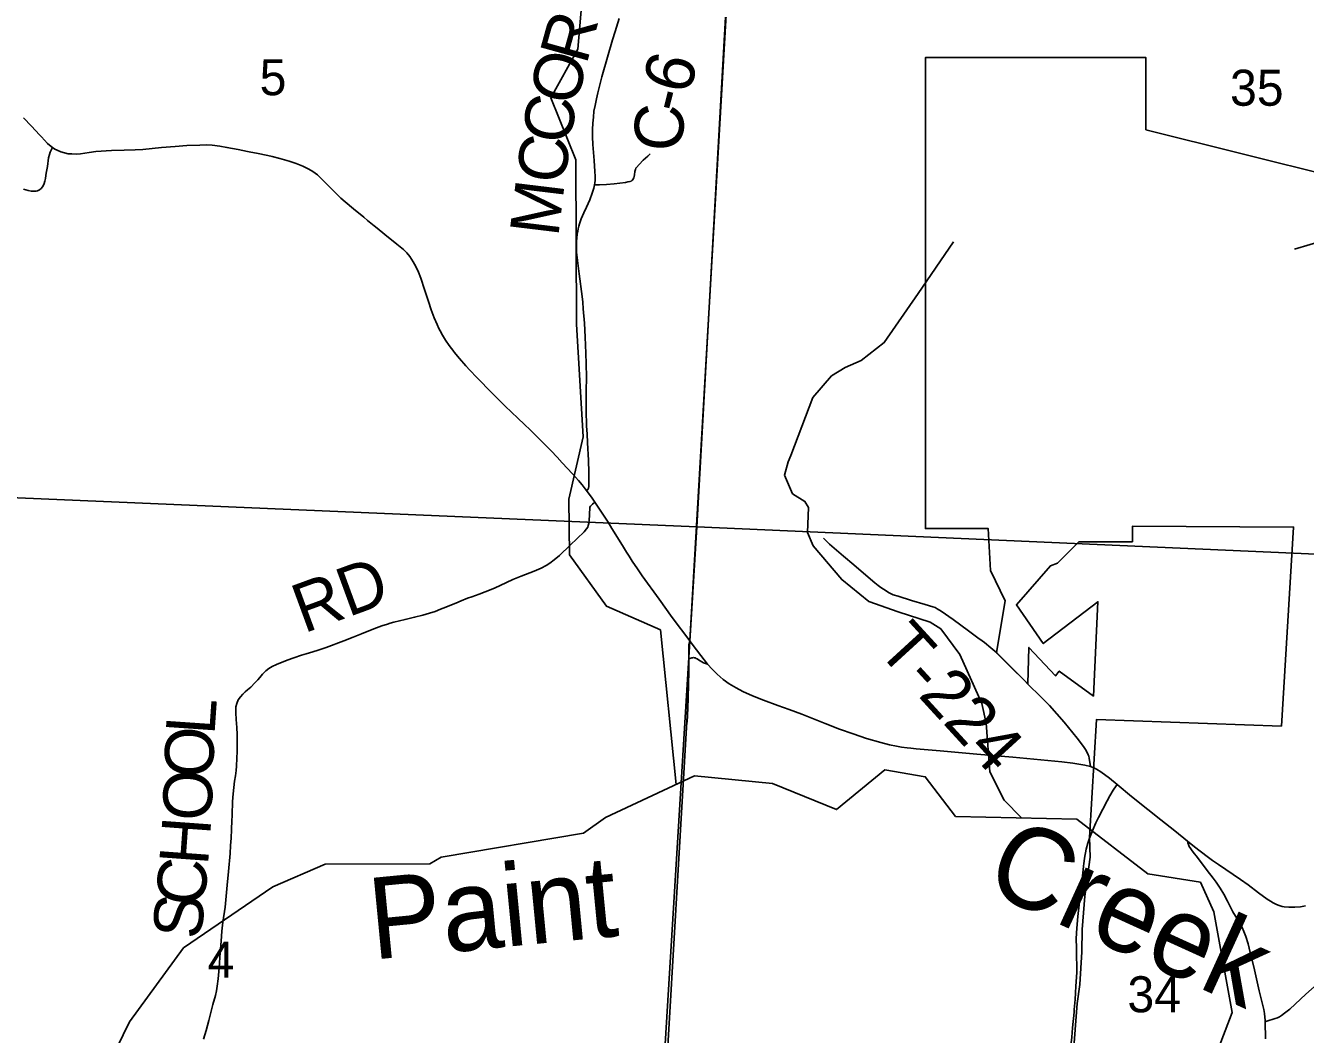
# Model space of a CAD drawing. Extents: x 0 to 34, y 0 to 22.
# Drawn here: x 26.889 to 28.376, y 19.422 to 20.594 of the extents above; entities that cross this region are included whole.
import ezdxf

# ---------------------------------------------------------------- set-up
doc = ezdxf.new("R2010")
doc.units = 0
for name, color, linetype in [('Default', 7, 'Continuous'), ('GM_X_City_Street', 7, 'Continuous'), ('GM_X_County_Road', 7, 'Continuous'), ('GM_X_County_Road_Text', 7, 'Continuous'), ('GM_X_Minor_River', 7, 'Continuous'), ('GM_X_Minor_River_Text', 7, 'Continuous'), ('GM_X_Section', 7, 'Continuous'), ('GM_X_Section_Text', 7, 'Continuous'), ('GM_X_State_Route', 7, 'Continuous'), ('GM_X_Township_Road', 7, 'Continuous'), ('GM_X_Township_Road_Text', 7, 'Continuous')]:
    doc.layers.add(name, color=color, linetype=linetype)

msp = doc.modelspace()

# ---------------------------------------------------------------- linework, layer by layer
at = {"layer": 'Default'}
for points in [[(27.477, 16.8624), (27.5436, 17.9511), (27.5778, 18.4732), (27.5831, 18.5542), (27.5939, 18.7192), (27.6065, 18.9313), (27.6117, 19.011), (27.6573, 19.7849), (27.6577, 19.7927), (27.658, 19.8018), (27.6584, 19.8127), (27.6591, 19.8289), (27.6592, 19.8432), (27.6592, 19.8474), (27.6594, 19.8586), (27.6594, 19.8591), (27.6594, 19.8627), (27.6594, 19.867), (27.6595, 19.8705), (27.6597, 19.8748), (27.6605, 19.8792), (27.7198, 20.9), (23.5167, 20.9)], [(30.3167, 20.9), (27.7198, 20.9), (27.6605, 19.8792), (27.6597, 19.8748), (27.6595, 19.8705), (27.6594, 19.867), (27.6594, 19.8627), (27.6594, 19.8591), (27.6594, 19.8586), (27.6592, 19.8474), (27.6592, 19.8432), (27.6591, 19.8289), (27.6584, 19.8127), (27.658, 19.8018), (27.6577, 19.7927), (27.6573, 19.7849), (27.6117, 19.011), (27.6065, 18.9313), (27.5939, 18.7192), (27.5831, 18.5542), (27.5778, 18.4732), (27.5436, 17.9511), (27.477, 16.8624)], [(28.5231, 20.3898), (28.1905, 20.4727), (28.1905, 20.5566), (27.9343, 20.5566), (27.9343, 20.0093), (28.0074, 20.0093), (28.0099, 19.9608), (28.0271, 19.9252), (28.0171, 19.8655), (28.0535, 19.8288), (28.0546, 19.8713), (28.0855, 19.8381), (28.0899, 19.8438), (28.1295, 19.8147), (28.1349, 19.9243), (28.0712, 19.8757), (28.0402, 19.9208), (28.0797, 19.9661), (28.0877, 19.9691), (28.1128, 19.9941), (28.1749, 19.9941), (28.1749, 20.0121), (28.3622, 20.011), (28.3481, 19.7799), (28.133, 19.7873), (28.125, 19.6502), (28.1259, 19.6275), (28.1196, 19.5821), (28.1165, 19.5435), (28.116, 19.5175), (28.1139, 19.4796), (28.1107, 19.4577), (28.1061, 19.3966)]]:
    msp.add_lwpolyline(points, dxfattribs=at)
for points in [[(27.7187, 20.9), (26.6756, 20.9), (26.6253, 20.056), (27.6689, 20.0112)], [(28.7599, 20.9), (27.7187, 20.9), (27.6689, 20.0112), (28.6954, 19.9659)]]:
    msp.add_lwpolyline(points, close=True, dxfattribs=at)
at = {"layer": 'GM_X_City_Street'}
msp.add_lwpolyline([(28.3292, 19.4362), (28.3309, 19.4368), (28.3409, 19.4399), (28.3433, 19.4408), (28.3458, 19.442), (28.3482, 19.4434), (28.3517, 19.4462), (28.3577, 19.4511), (28.3765, 19.4685), (28.3897, 19.4798), (28.403, 19.4914), (28.4154, 19.5023), (28.4223, 19.5084), (28.4325, 19.5178), (28.4395, 19.5243), (28.452, 19.5355), (28.4605, 19.5432), (28.486, 19.5663), (28.4944, 19.5738), (28.5134, 19.5917), (28.5225, 19.6007), (28.5244, 19.6031), (28.5257, 19.6053), (28.527, 19.6082)], dxfattribs=at)
at = {"layer": 'GM_X_County_Road'}
for points in [[(27.5406, 20.0534), (27.5422, 20.0547), (27.5431, 20.0562), (27.5433, 20.0581), (27.5433, 20.0619), (27.5432, 20.0744), (27.5429, 20.0889), (27.5418, 20.1088), (27.5412, 20.1194), (27.5408, 20.1283), (27.5403, 20.147), (27.5404, 20.169), (27.5405, 20.1853), (27.5404, 20.2006), (27.54, 20.2131), (27.539, 20.2319), (27.5381, 20.248), (27.5368, 20.2648), (27.5362, 20.2723), (27.5355, 20.279), (27.5319, 20.3054), (27.53, 20.3209), (27.5291, 20.3306), (27.5289, 20.3374), (27.5291, 20.3425), (27.5293, 20.3473), (27.5298, 20.3515), (27.5304, 20.3547), (27.531, 20.3575), (27.5317, 20.3605), (27.5326, 20.3634), (27.5346, 20.3693), (27.5376, 20.3761), (27.5408, 20.3829), (27.5445, 20.3913), (27.5473, 20.3989), (27.5491, 20.4049), (27.55, 20.4086), (27.5503, 20.4109), (27.5505, 20.4136), (27.5506, 20.4189), (27.5504, 20.4243), (27.5494, 20.4369), (27.5479, 20.4556), (27.5476, 20.4643), (27.5476, 20.4731), (27.548, 20.4804), (27.5486, 20.4874), (27.5493, 20.4943), (27.5505, 20.5009), (27.5521, 20.5085), (27.5538, 20.5157), (27.5585, 20.5341), (27.565, 20.5572), (27.571, 20.5772), (27.5739, 20.5869), (27.5786, 20.6018)], [(28.3296, 19.4164), (28.3292, 19.4362), (28.3291, 19.4378), (28.3283, 19.4459), (28.3276, 19.4506), (28.3266, 19.4551), (28.3222, 19.4721), (28.3159, 19.5002), (28.3119, 19.5167), (28.3093, 19.5267), (28.3066, 19.5352), (28.3045, 19.5412), (28.3025, 19.5458), (28.2966, 19.5559), (28.2916, 19.5642), (28.2852, 19.5766), (28.2811, 19.5845), (28.277, 19.5914), (28.2721, 19.5986), (28.2688, 19.6031), (28.2619, 19.6122), (28.2505, 19.627), (28.2456, 19.6332), (28.2409, 19.6401), (28.2399, 19.6421), (28.2393, 19.644), (28.239, 19.6462)]]:
    msp.add_lwpolyline(points, dxfattribs=at)
at = {"layer": 'GM_X_Minor_River'}
for points in [[(27.6449, 19.712), (27.6264, 19.8916), (27.5638, 19.9191), (27.5209, 19.9787), (27.52, 20.0436), (27.5369, 20.1158), (27.5291, 20.2467), (27.5281, 20.4376), (27.4991, 20.5098), (27.5306, 20.5663), (27.5352, 20.6206)], [(28.0459, 19.6732), (28.0258, 19.6937), (28.0091, 19.7268), (28.005, 19.7834), (28, 19.8059), (27.9743, 19.8632), (27.9523, 19.8929), (27.9398, 19.9004), (27.9027, 19.9126), (27.8685, 19.9247), (27.8371, 19.9501), (27.8041, 19.9893), (27.7973, 20.0048), (27.7985, 20.0337), (27.7943, 20.0409), (27.7799, 20.0497), (27.7708, 20.0713), (27.775, 20.0869), (27.778, 20.0941), (27.8034, 20.1618), (27.8254, 20.1866), (27.841, 20.1965), (27.8599, 20.2045), (27.8865, 20.2254), (27.9259, 20.2825), (27.9669, 20.3426)], [(28.2674, 19.3862), (28.2909, 19.4471), (28.2696, 19.5642), (28.254, 19.5986), (28.1927, 19.6083), (28.1103, 19.6716), (27.9694, 19.6749), (27.9342, 19.7209), (27.8871, 19.7289), (27.8311, 19.6828), (27.7567, 19.7133), (27.6662, 19.7219), (27.5625, 19.6736), (27.5373, 19.6555), (27.3717, 19.6275), (27.3585, 19.6198), (27.2371, 19.6194), (27.1763, 19.5931), (27.0725, 19.522), (27.0098, 19.4364), (26.9651, 19.3449)]]:
    msp.add_lwpolyline(points, dxfattribs=at)
at = {"layer": 'GM_X_Section'}
for points in [[(27.6689, 20.0112), (27.6061, 18.9865), (26.5652, 19.0298), (26.5757, 19.2125), (26.6008, 19.6356), (26.6253, 20.056)], [(27.6689, 20.0112), (28.6954, 19.9659), (28.635, 19.0454), (28.6278, 19.0396), (28.6176, 19.0309), (28.6078, 19.0218), (28.5961, 19.0123), (28.5772, 18.9948), (28.5545, 18.9735), (28.5372, 18.9571), (28.5304, 18.9506), (28.5239, 18.9438), (27.6061, 18.9865)]]:
    msp.add_lwpolyline(points, close=True, dxfattribs=at)
at = {"layer": 'GM_X_State_Route'}
for points in [[(26.8863, 20.4867), (26.8956, 20.4767), (26.9051, 20.4669), (26.9072, 20.4646), (26.9145, 20.4569), (26.9188, 20.4532), (26.9201, 20.4522), (26.9229, 20.4502), (26.9257, 20.4488), (26.9297, 20.4471), (26.934, 20.4458), (26.9383, 20.4449), (26.9427, 20.4446), (26.9478, 20.4445), (26.9528, 20.4449), (26.9626, 20.4464), (26.9706, 20.4474), (26.9887, 20.4487), (27.0036, 20.4491), (27.0163, 20.4494), (27.025, 20.4499), (27.0468, 20.4519), (27.0628, 20.4533), (27.0764, 20.4543), (27.0913, 20.4549), (27.0993, 20.455), (27.1055, 20.4547), (27.1146, 20.4536), (27.1228, 20.4521), (27.1359, 20.4496), (27.1468, 20.4474), (27.1505, 20.4467), (27.1571, 20.4454), (27.1705, 20.4427), (27.1753, 20.4416), (27.1843, 20.4394), (27.195, 20.4363), (27.2032, 20.4336), (27.2112, 20.4303), (27.2178, 20.427), (27.2225, 20.4243), (27.228, 20.4204), (27.232, 20.4166), (27.2359, 20.4127), (27.2397, 20.4087), (27.2428, 20.4057), (27.2472, 20.4013), (27.2552, 20.3934), (27.2604, 20.3889), (27.2699, 20.3809), (27.2819, 20.371), (27.2861, 20.3674), (27.2938, 20.3612), (27.2972, 20.3585), (27.3064, 20.351), (27.3202, 20.3396), (27.3242, 20.3366), (27.3279, 20.3334), (27.3318, 20.3296), (27.3354, 20.3254), (27.3394, 20.3192), (27.3424, 20.3139), (27.3455, 20.3072), (27.348, 20.3002), (27.3522, 20.2872), (27.3569, 20.2731), (27.3601, 20.2636), (27.3636, 20.2543), (27.3671, 20.2463), (27.3692, 20.2418), (27.3707, 20.239), (27.3733, 20.2341), (27.3768, 20.2282), (27.381, 20.222), (27.3863, 20.215), (27.3869, 20.2143)], [(27.3869, 20.2143), (27.3931, 20.2069), (27.4005, 20.1985), (27.4051, 20.1934), (27.4132, 20.1848), (27.431, 20.1665), (27.446, 20.1517), (27.4609, 20.1376), (27.4686, 20.1304), (27.4752, 20.1239), (27.4841, 20.1152), (27.4911, 20.1082), (27.4963, 20.1029), (27.4994, 20.0998), (27.5066, 20.0922), (27.5125, 20.0858), (27.5243, 20.073), (27.5313, 20.0652), (27.5357, 20.06), (27.5391, 20.0556), (27.5406, 20.0534), (27.547, 20.0445), (27.5502, 20.0399), (27.5589, 20.0271), (27.5626, 20.0214), (27.5656, 20.0167), (27.5702, 20.0093), (27.5767, 19.9988), (27.5835, 19.9877), (27.5871, 19.9819), (27.5901, 19.9772), (27.5938, 19.9714), (27.5997, 19.9626), (27.6054, 19.9545), (27.6249, 19.9272), (27.6402, 19.906), (27.6607, 19.8787)], [(27.6607, 19.8787), (27.6633, 19.8752), (27.6736, 19.8619), (27.6812, 19.8519), (27.6866, 19.8459), (27.6925, 19.84), (27.6995, 19.8341), (27.7062, 19.829), (27.7144, 19.8242), (27.7221, 19.8201), (27.7335, 19.8151), (27.7463, 19.8101), (27.7628, 19.8039), (27.7761, 19.7991), (27.7909, 19.7935), (27.818, 19.7829), (27.8346, 19.7764), (27.8503, 19.7709), (27.8658, 19.7656), (27.8825, 19.7607), (27.8928, 19.7581), (27.9008, 19.7565), (27.9067, 19.7554), (27.9133, 19.7545), (27.9174, 19.7541), (27.9237, 19.7535), (27.9377, 19.7522), (27.9517, 19.751), (27.994, 19.7474), (28.036, 19.7437), (28.0929, 19.7382), (28.1058, 19.7367), (28.1197, 19.7344), (28.1262, 19.733)], [(28.1262, 19.733), (28.1299, 19.7314), (28.133, 19.7297), (28.1382, 19.7265), (28.1481, 19.7195), (28.1572, 19.712), (28.174, 19.6981), (28.1928, 19.6828), (28.2078, 19.6709), (28.224, 19.6582), (28.239, 19.6462), (28.2469, 19.6397), (28.2618, 19.6282), (28.2679, 19.6238), (28.2749, 19.6189), (28.3006, 19.6015), (28.3095, 19.5954), (28.3215, 19.5861), (28.3315, 19.5787), (28.3353, 19.5763), (28.3383, 19.5746), (28.3416, 19.5728), (28.3441, 19.5719), (28.3464, 19.571), (28.349, 19.5704), (28.3513, 19.5699), (28.3568, 19.5693), (28.3637, 19.5693), (28.3703, 19.5699), (28.3761, 19.571)]]:
    msp.add_lwpolyline(points, dxfattribs=at)
at = {"layer": 'GM_X_Township_Road'}
for points in [[(26.8866, 20.4037), (26.8919, 20.4023), (26.8955, 20.4014), (26.8973, 20.4012), (26.8997, 20.4012), (26.901, 20.4014), (26.9027, 20.4019), (26.9049, 20.403), (26.9069, 20.4045), (26.9085, 20.4063), (26.9098, 20.4084), (26.9105, 20.4101), (26.9114, 20.4131), (26.912, 20.4161), (26.9126, 20.4197), (26.913, 20.4222), (26.9142, 20.4302), (26.9157, 20.44), (26.9165, 20.4439), (26.9176, 20.4465), (26.9201, 20.4522)], [(27.55, 20.4086), (27.5558, 20.4087), (27.564, 20.4091), (27.5728, 20.4099), (27.5861, 20.4115), (27.5888, 20.412), (27.5911, 20.4125), (27.5924, 20.413), (27.5934, 20.4137), (27.5943, 20.4146), (27.595, 20.4156), (27.5955, 20.4168), (27.5959, 20.4182), (27.5964, 20.4202), (27.5969, 20.4241), (27.5972, 20.4255), (27.5975, 20.4267), (27.598, 20.4279), (27.5987, 20.429), (27.6017, 20.4325), (27.6065, 20.4374), (27.6117, 20.4422), (27.6145, 20.4448)], [(28.3632, 20.3341), (28.3814, 20.3395), (28.3985, 20.3446), (28.4022, 20.3454), (28.4058, 20.346), (28.4101, 20.3463), (28.415, 20.346), (28.4186, 20.3453), (28.4227, 20.3439), (28.4285, 20.3418), (28.4409, 20.3379), (28.4553, 20.3334), (28.4683, 20.3297), (28.4778, 20.3262), (28.4912, 20.3198), (28.4954, 20.3179), (28.4994, 20.3164), (28.5045, 20.3146), (28.5098, 20.3132), (28.5107, 20.3132)], [(27.3126, 19.8993), (27.3166, 19.9005), (27.3299, 19.9037), (27.3408, 19.9063), (27.3504, 19.9086), (27.3582, 19.9109), (27.3646, 19.9131), (27.371, 19.9156), (27.3773, 19.9181), (27.3836, 19.9206), (27.3887, 19.9227), (27.395, 19.9252), (27.4025, 19.9283), (27.4072, 19.9299), (27.4118, 19.9316), (27.4159, 19.9331), (27.4229, 19.9357), (27.4338, 19.9401), (27.4478, 19.9467), (27.4551, 19.95), (27.4607, 19.9525), (27.4647, 19.9542), (27.4798, 19.9598), (27.4878, 19.9632), (27.4938, 19.9665), (27.498, 19.9691), (27.503, 19.9729), (27.5091, 19.9782), (27.5217, 19.9902), (27.5298, 19.9979), (27.5379, 20.0056), (27.5408, 20.0089), (27.542, 20.011), (27.5427, 20.0127), (27.5433, 20.0151), (27.5437, 20.02), (27.544, 20.0243), (27.5442, 20.0274), (27.5443, 20.0324), (27.5446, 20.0341), (27.5454, 20.0355), (27.5477, 20.0377), (27.5502, 20.0399)], [(27.8158, 19.998), (27.8231, 19.9913), (27.8391, 19.9773), (27.8512, 19.9671), (27.8652, 19.9551), (27.8758, 19.9464), (27.8796, 19.9433), (27.8826, 19.941), (27.8858, 19.9388), (27.8887, 19.9368), (27.8914, 19.9351), (27.8944, 19.9335), (27.8971, 19.9325), (27.9028, 19.9306), (27.9182, 19.9257), (27.9342, 19.921), (27.943, 19.9184), (27.9456, 19.9175), (27.948, 19.9161), (27.9528, 19.9133), (27.9665, 19.9037), (27.9755, 19.8972), (27.9844, 19.8906), (27.9923, 19.8848), (27.997, 19.8814), (27.9978, 19.8808)], [(27.0955, 19.4162), (27.0986, 19.4263), (27.1018, 19.4377), (27.1046, 19.4485), (27.1066, 19.4563), (27.1094, 19.4668), (27.1106, 19.4722), (27.1115, 19.4777), (27.1126, 19.4862), (27.1137, 19.499), (27.1148, 19.5167), (27.116, 19.5298), (27.117, 19.5417), (27.1181, 19.552), (27.1206, 19.5696), (27.1231, 19.5949), (27.1246, 19.6109), (27.1264, 19.6317), (27.127, 19.641), (27.1276, 19.6496), (27.1281, 19.6595), (27.1283, 19.6626), (27.1285, 19.6669), (27.1286, 19.6688), (27.1289, 19.6769), (27.1294, 19.6924), (27.13, 19.7011), (27.1318, 19.7159), (27.1327, 19.722), (27.1336, 19.7282), (27.1339, 19.7331), (27.1341, 19.7362), (27.1343, 19.7393), (27.1344, 19.7436), (27.1346, 19.7492), (27.1348, 19.7591), (27.1348, 19.7701), (27.1344, 19.7781), (27.1337, 19.7873), (27.133, 19.7953), (27.1331, 19.7996), (27.1333, 19.8021), (27.1343, 19.8062), (27.136, 19.8102), (27.1385, 19.8138), (27.1414, 19.817), (27.1441, 19.8195), (27.1469, 19.8219), (27.1506, 19.8252), (27.1554, 19.8299), (27.1587, 19.8336), (27.1611, 19.8364), (27.1643, 19.8402), (27.1682, 19.8441), (27.1716, 19.8467), (27.1753, 19.8489), (27.1803, 19.8513), (27.1928, 19.8563), (27.2007, 19.8593), (27.2095, 19.8621), (27.2148, 19.8637), (27.2225, 19.8661), (27.2289, 19.8682), (27.2383, 19.8713), (27.2586, 19.8787), (27.2695, 19.883), (27.2793, 19.887), (27.2937, 19.8929), (27.303, 19.8963), (27.3095, 19.8984), (27.3126, 19.8993)], [(27.6575, 19.7843), (27.6579, 19.7921), (27.6582, 19.8012), (27.6586, 19.8122), (27.6593, 19.8284), (27.6594, 19.8427), (27.6594, 19.8469), (27.6596, 19.8581), (27.6596, 19.8622), (27.6596, 19.8665), (27.6597, 19.87), (27.66, 19.8742), (27.6607, 19.8787)], [(27.9978, 19.8808), (28.0032, 19.8768), (28.0103, 19.8709), (28.0173, 19.8649), (28.0179, 19.8643)], [(27.6596, 19.8581), (27.6628, 19.8592), (27.6636, 19.8593), (27.665, 19.8594), (27.6659, 19.8592), (27.6669, 19.859), (27.668, 19.8585), (27.669, 19.8579), (27.6707, 19.8568), (27.6726, 19.8556), (27.6745, 19.8546), (27.6766, 19.8534), (27.6789, 19.8525), (27.6812, 19.8519)], [(28.0179, 19.8643), (28.0271, 19.8549), (28.0346, 19.8471), (28.0486, 19.8334), (28.0537, 19.8282), (28.0544, 19.8275)], [(28.0544, 19.8275), (28.0672, 19.8151), (28.0785, 19.8036), (28.0955, 19.7844), (28.1108, 19.7659), (28.1147, 19.7607), (28.119, 19.7548), (28.121, 19.7514), (28.1236, 19.7466), (28.1243, 19.7449), (28.1248, 19.7427), (28.1262, 19.733)], [(28.1252, 19.6497), (28.128, 19.6572), (28.1325, 19.6673), (28.1356, 19.6736), (28.1454, 19.6931), (28.1486, 19.6988), (28.1527, 19.7053), (28.1561, 19.7103), (28.1572, 19.712)], [(28.1183, 19.62), (28.1187, 19.6228), (28.1191, 19.6265), (28.1213, 19.6369), (28.1232, 19.6439), (28.1252, 19.6497)], [(28.1163, 19.6004), (28.1165, 19.6024), (28.1175, 19.6129), (28.1179, 19.6172), (28.1183, 19.62)], [(28.1074, 19.4505), (28.1082, 19.4623), (28.1093, 19.4777), (28.1103, 19.4936), (28.1105, 19.503), (28.1101, 19.5106), (28.1098, 19.5218), (28.1096, 19.5331), (28.1103, 19.5449), (28.1115, 19.5586), (28.1131, 19.5721), (28.1151, 19.5883), (28.1163, 19.6004)], [(28.1017, 19.3902), (28.1018, 19.3922), (28.1026, 19.4017), (28.1044, 19.4184), (28.1054, 19.4294), (28.1072, 19.4475), (28.1074, 19.4505)]]:
    msp.add_lwpolyline(points, dxfattribs=at)

# ---------------------------------------------------------------- texts
at = {"layer": 'GM_X_County_Road_Text'}
for s, rotation, p in [('R', 74.4803, (27.5404, 20.5472)), ('O', 76.2067, (27.5286, 20.499)), ('6', 75.1444, (27.6597, 20.512)), ('C', 80.5511, (27.5211, 20.4541)), ('-', 75.8093, (27.6541, 20.4898)), ('C', 86.4285, (27.6516, 20.4463)), ('C', 82.4611, (27.5151, 20.4084)), ('M', 83.0926, (27.5077, 20.3473))]:
    msp.add_text(s, height=0.0568, rotation=rotation, dxfattribs=at).set_placement(p)
at = {"layer": 'GM_X_Minor_River_Text'}
for s, height, rotation, p in [('Creek', 0.09469, 335.5162, (27.9995, 19.5908)), ('Paint', 0.0947, 5.5114, (27.2923, 19.5084))]:
    msp.add_text(s, height=height, rotation=rotation, dxfattribs=at).set_placement(p)
at = {"layer": 'GM_X_Section_Text'}
for s, height, p in [('5', 0.0419, (27.1608, 20.5128)), ('35', 0.04186, (28.2883, 20.5006)), ('4', 0.0419, (27.1004, 19.4876)), ('34', 0.04186, (28.1691, 19.4473))]:
    msp.add_text(s, height=height, rotation=0, dxfattribs=at).set_placement(p)
at = {"layer": 'GM_X_Township_Road_Text'}
for s, height, rotation, p in [('RD', 0.05682, 20.1431, (27.2122, 19.8873)), ('T-224', 0.05682, 312.4626, (27.8766, 19.8681)), ('L', 0.0568, 86.0542, (27.1083, 19.7687)), ('O', 0.0568, 88.0202, (27.1066, 19.7193)), ('O', 0.0568, 87.6881, (27.1046, 19.669)), ('H', 0.0568, 85.8751, (27.1008, 19.6171)), ('C', 0.0568, 84.6231, (27.0964, 19.5693)), ('S', 0.0568, 84.5561, (27.0927, 19.5311))]:
    msp.add_text(s, height=height, rotation=rotation, dxfattribs=at).set_placement(p)

doc.saveas('drawing.dxf')
